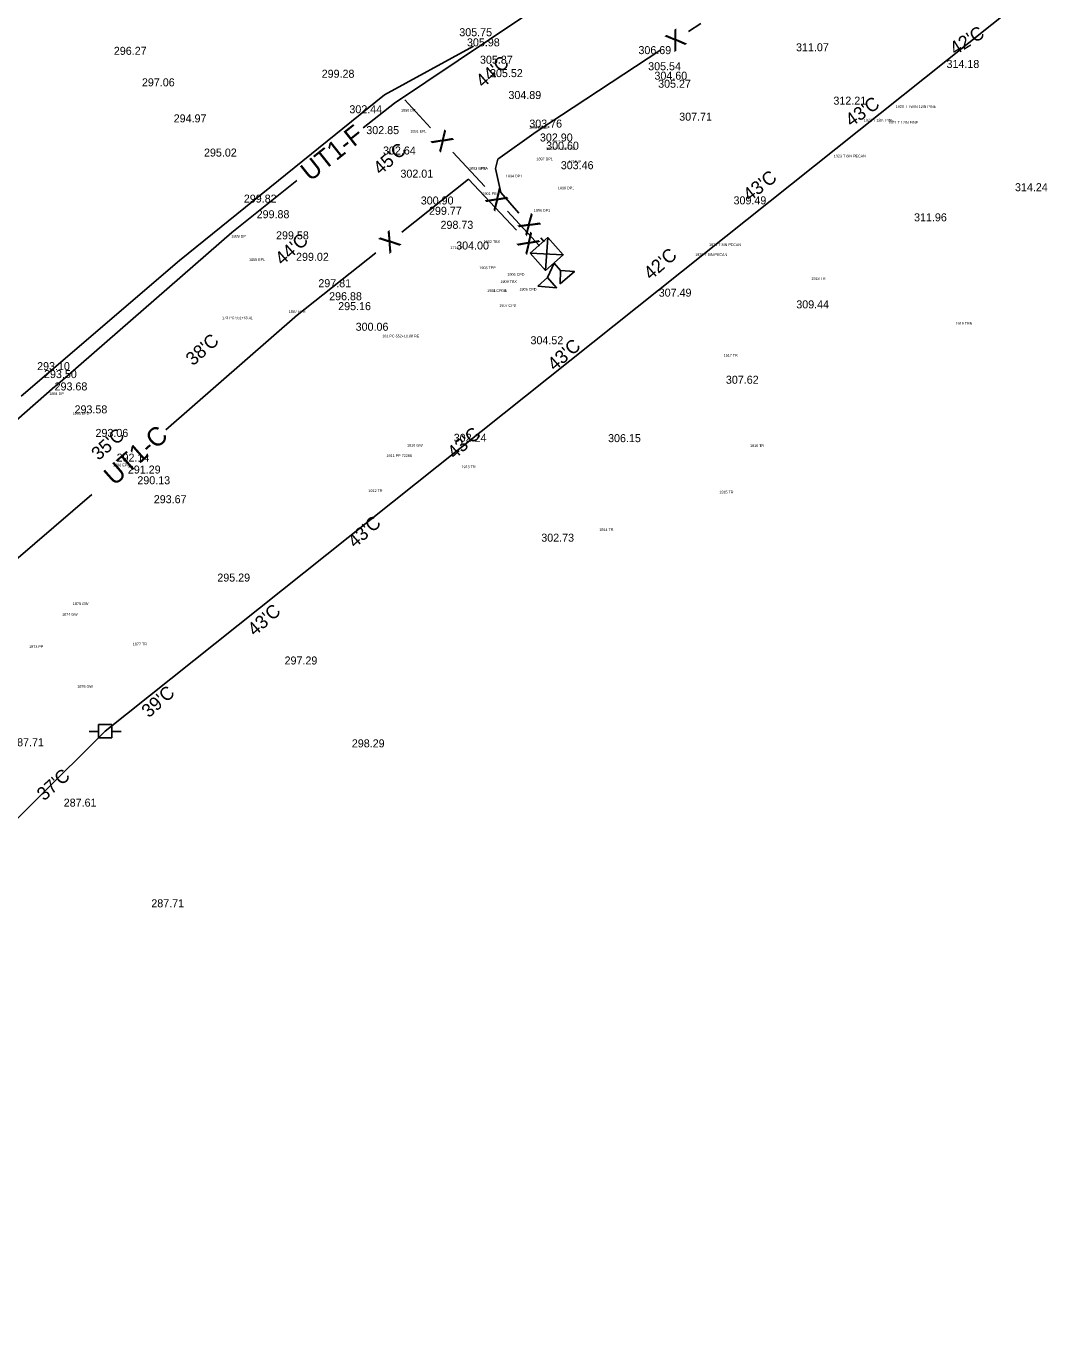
# Model space of a CAD drawing. Extents: x 49683 to 58852, y 49596 to 54801.
# Drawn here: x 55957.1 to 56343.4, y 53396.3 to 53890.3 of the extents above; entities that cross this region are included whole.
import ezdxf

# ---------------------------------------------------------------- set-up
doc = ezdxf.new("R2010")
doc.units = 0
for name, color, linetype in [('Level 10', 7, 'Continuous'), ('Level 2', 7, 'Continuous'), ('Level 3', 7, 'Continuous'), ('Level 32', 7, 'Continuous'), ('Level 4', 7, 'Continuous'), ('Level 48', 7, 'Continuous'), ('Level 51', 7, 'Continuous'), ('Level 53', 7, 'Continuous'), ('Level 56', 7, 'Continuous'), ('Level 58', 7, 'Continuous'), ('Level 59', 7, 'Continuous'), ('Level 61', 7, 'Continuous'), ('Level 62', 7, 'Continuous'), ('Level 9', 7, 'Continuous')]:
    doc.layers.add(name, color=color, linetype=linetype)

# ---------------------------------------------------------------- blocks, each defined once
blk = doc.blocks.new('PP')
at = {"layer": 'Level 9'}
for p, q in [((2.53, 2.45), (-2.47, 2.45)), ((-2.47, 2.45), (-2.47, -2.55)), ((2.53, -2.55), (2.53, 2.45)), ((-5.91, -0.11), (-2.44, -0.11)), ((-2.47, -2.55), (2.53, -2.55)), ((2.45, -0.11), (6.09, -0.11))]:
    blk.add_line(p, q, dxfattribs=at)

msp = doc.modelspace()

# ---------------------------------------------------------------- linework, layer by layer
at = {"layer": 'Level 10'}
msp.add_lwpolyline([(55755.61, 53396.28), (55986.6, 53626.23), (56343.45, 53910.79)], dxfattribs=at)
at = {"layer": 'Level 2'}
for p, q in [((56205.18, 53888.4), (56209.79, 53891.44)), ((56148.16, 53850.77), (56194.78, 53881.54)), ((56108.49, 53852.35), (56098.85, 53862.8)), ((56133.75, 53840.58), (56148.16, 53850.77)), ((56128.85, 53830.29), (56116.94, 53843.19)), ((56097.79, 53813.23), (56122.69, 53833.01)), ((56140.69, 53813.95), (56122.69, 53833.01)), ((56149.35, 53808.06), (56137.3, 53821.13)), ((56152.51, 53811.18), (56151.62, 53798.86)), ((56058.52, 53782.05), (56088.04, 53805.49)), ((56145.89, 53805.31), (56158.23, 53804.72)), ((56154.79, 53801.56), (56152.32, 53796.27)), ((56154.79, 53801.56), (56157.22, 53798.78)), ((56009.41, 53739.09), (56058.71, 53782.2)), ((55906.59, 53650.29), (55981.6, 53714.92))]:
    msp.add_line(p, q, dxfattribs=at)
for points in [[(56091.34, 53864.62), (56124.68, 53882.92)], [(55955.17, 53751.74), (56014.47, 53802.53), (56091.34, 53864.62)], [(56141.62, 53820.38), (56134.86, 53828.08), (56132.83, 53837.03), (56133.75, 53840.58)], [(56151.09, 53809.6), (56149.84, 53811.02)]]:
    msp.add_lwpolyline(points, dxfattribs=at)
for points in [[(56145.89, 53805.31), (56152.51, 53811.18), (56158.23, 53804.72), (56151.62, 53798.86)], [(56157.03, 53793.87), (56162.41, 53798.52), (56157.22, 53798.78)], [(56148.68, 53792.96), (56155.77, 53792.38), (56152.32, 53796.27)]]:
    msp.add_lwpolyline(points, close=True, dxfattribs=at)
at = {"layer": 'Level 3'}
for p, q in [((56095.05, 53861.61), (56199.41, 53931.58)), ((56083.29, 53852.26), (56095.05, 53861.61)), ((56034.09, 53813.12), (56058.49, 53832.53)), ((55967.85, 53755.38), (56034.09, 53813.12)), ((55924.21, 53717.11), (55967.82, 53755.35))]:
    msp.add_line(p, q, dxfattribs=at)

# ---------------------------------------------------------------- block references
at = {"layer": 'Level 10'}
msp.add_blockref('PP', (55986.6, 53626.23), dxfattribs=at)

# ---------------------------------------------------------------- texts
at = {"layer": 'Level 2'}
msp.add_text('UT1-C', height=7, rotation=41.4177, dxfattribs=at).set_placement((55990.03, 53717.9))
at = {"layer": 'Level 32'}
for s, p in [('305.75', (56119.3, 53886.64)), ('296.27', (55989.89, 53879.67)), ('305.98', (56122.18, 53882.84)), ('306.69', (56186.41, 53879.93)), ('311.07', (56245.46, 53881)), ('305.87', (56127.05, 53876.34)), ('305.54', (56190.06, 53873.89)), ('314.18', (56301.83, 53874.75)), ('299.28', (56067.75, 53871.08)), ('305.52', (56130.81, 53871.31)), ('304.60', (56192.41, 53870.35)), ('297.06', (56000.41, 53867.86)), ('305.27', (56193.79, 53867.33)), ('304.89', (56137.71, 53863.1)), ('312.21', (56259.45, 53860.99)), ('294.97', (56012.31, 53854.35)), ('302.44', (56078.12, 53857.77)), ('307.71', (56201.69, 53855)), ('302.85', (56084.47, 53849.95)), ('303.76', (56145.53, 53852.39)), ('302.90', (56149.51, 53847.19)), ('300.60', (56151.83, 53844.12)), ('295.02', (56023.66, 53841.54)), ('302.64', (56090.72, 53842.31)), ('303.46', (56157.32, 53836.8)), ('302.01', (56097.25, 53833.63)), ('299.82', (56038.59, 53824.28)), ('314.24', (56327.48, 53828.56)), ('300.90', (56104.87, 53823.58)), ('299.77', (56107.95, 53819.72)), ('309.49', (56222.04, 53823.63)), ('299.88', (56043.39, 53818.43)), ('298.73', (56112.27, 53814.46)), ('311.96', (56289.67, 53817.27)), ('299.58', (56050.66, 53810.52)), ('304.00', (56118.14, 53806.71)), ('299.02', (56058.15, 53802.47)), ('297.81', (56066.5, 53792.58)), ('296.88', (56070.54, 53787.69)), ('307.49', (56194.01, 53789.04)), ('309.44', (56245.55, 53784.64)), ('295.16', (56073.94, 53783.98)), ('300.06', (56080.48, 53776.26)), ('304.52', (56145.98, 53771.2)), ('293.10', (55961.15, 53761.5)), ('293.50', (55963.74, 53758.52)), ('307.62', (56219.18, 53756.4)), ('293.68', (55967.69, 53753.89)), ('293.58', (55975.17, 53745.29)), ('293.06', (55983.02, 53736.47)), ('302.24', (56117.22, 53734.64)), ('306.15', (56175.04, 53734.51)), ('292.14', (55990.92, 53727.21)), ('291.29', (55995.14, 53722.74)), ('290.13', (55998.7, 53718.73)), ('293.67', (56004.85, 53711.62)), ('302.73', (56150.02, 53697.21)), ('295.29', (56028.66, 53682.26)), ('297.29', (56053.85, 53651.19)), ('287.71', (55951.42, 53620.54)), ('298.29', (56079.05, 53620.12)), ('287.61', (55971.11, 53597.91)), ('287.71', (56003.93, 53560.19))]:
    msp.add_text(s, height=3, dxfattribs=at).set_placement(p)
at = {"layer": 'Level 4'}
for s, rotation, p in [('X', 33.4211, (56199.63, 53880.55)), ('UT1-F', 38.5023, (56063.41, 53831.97)), ('X', 312.6938, (56108.29, 53847.4)), ('X', 312.6938, (56128.65, 53825.34)), ('X', 131.2906, (56150.16, 53815.96)), ('X', 38.4575, (56092.96, 53804.92)), ('X', 313.3433, (56140.54, 53809))]:
    msp.add_text(s, height=7, rotation=rotation, dxfattribs=at).set_placement(p)
at = {"layer": 'Level 48'}
for s, rotation, p in [("42'C", 32.2339, (56305.06, 53879.36)), ("44'C", 41.14, (56128.15, 53867.07)), ("43'C", 35.2026, (56266.16, 53852.49)), ("45'C", 41.6334, (56089.77, 53834.41)), ("43'C", 38.1713, (56228.07, 53824.5)), ("44'C", 41.6334, (56052.99, 53800.53)), ("42'C", 41.14, (56191.06, 53795.05)), ("38'C", 41.6334, (56019.54, 53762.9)), ("43'C", 41.6334, (56155.06, 53760.96)), ("35'C", 41.6334, (55984.18, 53727.42)), ("43'C", 41.6334, (56117.55, 53727.9)), ("43'C", 41.6334, (56080.23, 53694.63)), ("43'C", 41.6334, (56042.71, 53661.57)), ("39'C", 41.6334, (56003, 53630.98)), ("37'C", 41.6334, (55963.78, 53599.84))]:
    msp.add_text(s, height=5, rotation=rotation, dxfattribs=at).set_placement(p)
at = {"layer": 'Level 51'}
for s, p in [('173 PC 551+63.41 ', (56030.42, 53780.6)), ('181 PC 552+10.88 RE ', (56090.45, 53773.76))]:
    msp.add_text(s, height=1, dxfattribs=at).set_placement(p)
at = {"layer": 'Level 53'}
for s, p in [('1891 EPL ', (56100.96, 53850.53)), ('1899 EPR ', (56145.4, 53851.95)), ('1892 EPR ', (56122.95, 53836.6)), ('1888 EPL ', (56040.5, 53802.43)), ('1887 EPR ', (56055.41, 53782.96)), ('1885 EPL ', (55974.42, 53744.84)), ('1886 EPR ', (55989.61, 53725.42))]:
    msp.add_text(s, height=1, dxfattribs=at).set_placement(p)
at = {"layer": 'Level 56'}
for s, p in [('1900 PA 18IN RC ', (56151.85, 53844.05)), ('1901 PB ', (56127.97, 53827.15))]:
    msp.add_text(s, height=1, dxfattribs=at).set_placement(p)
at = {"layer": 'Level 58'}
for s, p in [('1890 DP ', (56097.49, 53858.41)), ('1898 DP1B ', (56145.4, 53851.95)), ('1893 DP1A ', (56122.95, 53836.6)), ('1897 DP1 ', (56148.21, 53840.14)), ('1894 DP1 ', (56136.75, 53833.71)), ('1896 DP1 ', (56156.24, 53829.22)), ('1895 DP1 ', (56147.2, 53820.85)), ('1889 DP ', (56033.94, 53811.18)), ('1905 CPD ', (56137.33, 53796.87)), ('1906 CPD ', (56141.86, 53791.31)), ('1904 CPDA ', (56129.74, 53790.77)), ('1908 CPDB ', (56129.74, 53790.77)), ('1907 CPD ', (56134.27, 53785.21)), ('1884 DP ', (55965.73, 53752.18))]:
    msp.add_text(s, height=1, dxfattribs=at).set_placement(p)
at = {"layer": 'Level 59'}
for s, p in [('1902 TBX ', (56128.43, 53809.1)), ('1903 TPP ', (56126.79, 53799.35)), ('1909 TBX ', (56134.73, 53794.2)), ('1910 GW ', (56099.74, 53732.81)), ('1911 PP 72288 ', (56092.03, 53728.94)), ('1875 GW ', (55974.53, 53673.47)), ('1874 GW ', (55970.48, 53669.46)), ('1873 PP ', (55958.16, 53657.32)), ('1876 GW ', (55976.22, 53642.48))]:
    msp.add_text(s, height=1, dxfattribs=at).set_placement(p)
at = {"layer": 'Level 61'}
for s, p in [('1920 T TWIN 12IN PINE ', (56282.78, 53859.79)), ('1922 T 12IN PINE ', (56270.85, 53854.68)), ('1921 T 12IN PINE ', (56280.04, 53853.81)), ('1923 T 8IN PECAN ', (56259.6, 53841.22)), ('1924 T 8IN PECAN ', (56212.86, 53808.01)), ('1925 T 8IN PECAN ', (56207.69, 53804.29)), ('1918 TR ', (56251.21, 53795.33)), ('1919 TRB ', (56305.22, 53778.48)), ('1917 TR ', (56218.32, 53766.53)), ('1916 TR ', (56228.2, 53732.68)), ('1913 TR ', (56120.13, 53724.76)), ('1912 TR ', (56085.22, 53715.79)), ('1915 TR ', (56216.72, 53715.3)), ('1914 TR ', (56171.75, 53701.22)), ('1877 TR ', (55996.99, 53658.35))]:
    msp.add_text(s, height=1, dxfattribs=at).set_placement(p)
at = {"layer": 'Level 62'}
for s, p in [('1715 IP ', (56160.27, 53839.1)), ('1716 IP ', (56115.99, 53806.93))]:
    msp.add_text(s, height=1, dxfattribs=at).set_placement(p)

doc.saveas('drawing.dxf')
